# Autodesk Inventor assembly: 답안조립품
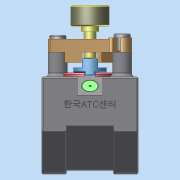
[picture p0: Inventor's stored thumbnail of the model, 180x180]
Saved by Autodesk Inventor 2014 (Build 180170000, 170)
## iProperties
Created: 2025-02
Part Number: 답안조립품
Document SubType Name: Assembly
Designer: dg
Author: dg
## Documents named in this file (9)
- C:\Users\dg\Desktop\750203V1005\답안조립품.iam
- C:\Users\dg\Desktop\750203V1005\본체.ipt
- C:\Users\dg\Desktop\750203V1005\가져온 구성요소\드릴부시\드릴부시.ipt
- C:\Users\dg\Desktop\750203V1005\가져온 구성요소\서포터\서포터.ipt
- C:\Users\dg\Desktop\750203V1005\가져온 구성요소\조\조.ipt
- C:\Users\dg\Desktop\750203V1005\가져온 구성요소\노브\노브.ipt
- C:\Users\dg\Desktop\750203V1005\가져온 구성요소\고정핀\고정핀.ipt
- C:\Users\dg\Desktop\750203V1005\가져온 구성요소\가공품\가공품.ipt
- C:\Users\dg\Desktop\750203V1005\가져온 구성요소\스트리퍼 볼트 M6x10\스트리퍼 볼트 M6x10.ipt
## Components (2 placed, 2 different names)
1. 가공품:1
2. 고정핀:1
